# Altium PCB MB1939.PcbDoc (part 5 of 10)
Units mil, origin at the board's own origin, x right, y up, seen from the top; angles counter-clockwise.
Board outline 5910.64 x 4335.93 mil, 6 copper layers (Top Layer, l2_GND, L3_SIG, L4_VCC, L5_GND, Bottom Layer), stack 58.424 mil thick; 635 components, 489 nets, 2289 pads, 1388 vias.
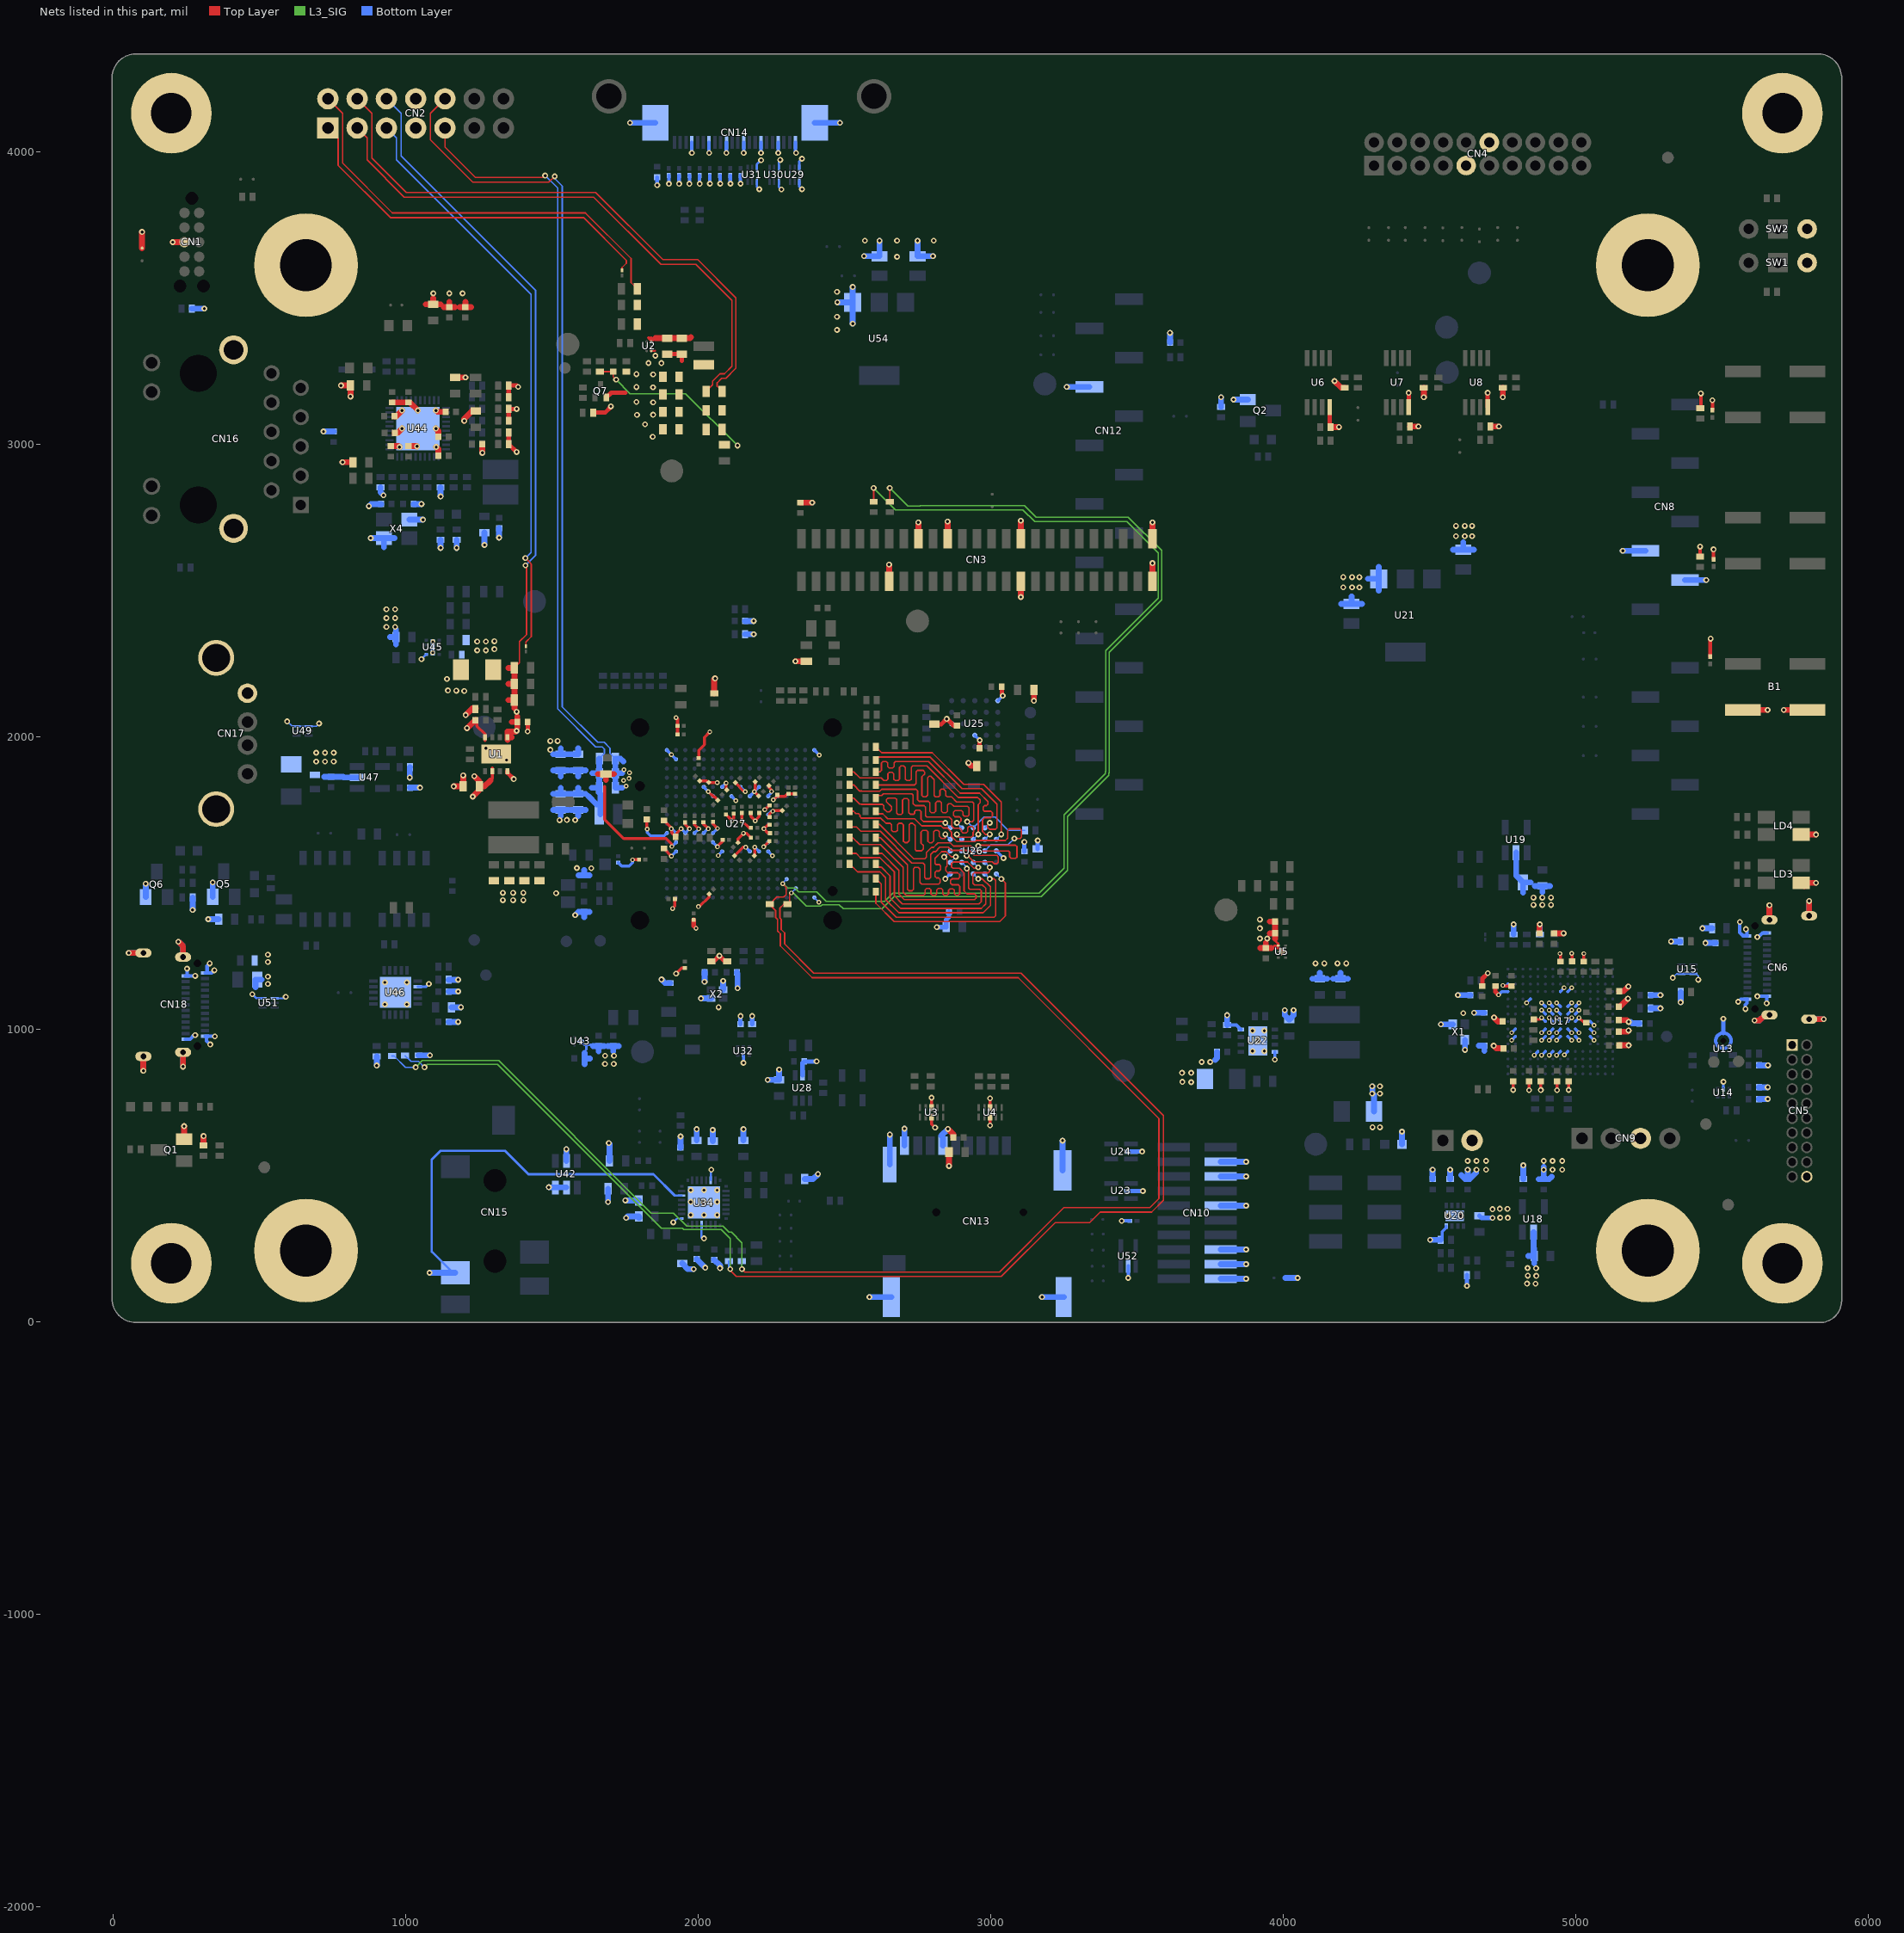
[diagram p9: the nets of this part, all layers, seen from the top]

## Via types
v1: diameter 20, hole 10, Top Layer to Bottom Layer, tented both sides, 1072 vias
v2: diameter 16, hole 8, Top Layer to Bottom Layer, tented both sides, 316 vias

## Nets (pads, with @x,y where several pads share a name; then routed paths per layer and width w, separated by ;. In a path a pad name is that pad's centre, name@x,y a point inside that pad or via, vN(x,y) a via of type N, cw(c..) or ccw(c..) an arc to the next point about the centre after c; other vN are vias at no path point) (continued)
GND: B1.3 B1.4 C1.1 C2.1 C3.1 C4.1 C5.1 C6.1 C7.1 C8.1 C9.1 C10.1 C11.1 C12.1 C13.1 C14.1 C15.1 C16.1 C17.1 C18.1 C19.2 C20.1 C21.1 C22.1 C24.1 C25.1 C26.1 C28.1 C29.1 C31.1 C32.1 C33.2 C34.1 C35.1 C36.1 C37.1 C38.1 C39.1 C40.1 C41.1 C42.1 C43.2 C44.1 C45.1 C46.1 C47.1 C48.1 C49.1 C50.1 C51.1 C52.1 C54.1 C55.1 C56.1 C57.1 C58.1 C59.1 C60.1 C61.1 C62.1 C63.1 C64.1 C65.1 C66.1 C67.1 C68.1 C69.1 C70.1 C71.1 C72.1 C73.1 C74.1 C75.1 C76.1 C77.1 C78.1 C79.1 C80.1 C81.2 C84.1 C85.2 C86.1 C87.1 C88.1 C89.1 C90.1 C91.1 C92.1 C94.1 C95.1 C96.2 C97.2 C98.2 C99.2 C100.2 C101.2 C102.2 C103.2 C104.2 C105.2 C106.2 C107.2 C108.2 C109.2 C110.2 C111.2 C112.2 C113.2 C114.2 C115.1 C116.1 C117.1 C118.1 C119.1 C120.2 C121.1 C122.1 C123.1 C124.1 C125.1 C126.1 C127.2 C128.1 C129.1 C130.1 C131.1 C132.1 C133.1 C134.1 C135.1 C136.1 C137.1 C138.1 C139.1 C140.2 C141.1 C142.1 C143.1 C144.1 C145.1 C146.1 C147.1 C148.1 C149.1 C150.1 C151.1 C152.1 C153.1 C155.1 C158.2 C159.1 C161.1 C162.1 C163.2 C167.2 C168.1 C169.1 C171.1 C172.1 C173.1 C174.1 C175.1 C176.1 C177.1 C178.1 C179.1 C180.1 C181.1 C183.1 C185.2 C186.1 C187.1 C188.1 C189.1 C190.1 C191.1 C193.1 C194.2 C195.1 C197.1 C198.1 C199.1 C200.1 C201.1 CN1.3 CN2.7 CN2.8 CN3.1 CN3.2 CN3.19 CN3.20 CN3.30 CN3.34 CN3.37 CN4.5 CN4.16 CN5.1 CN5.20 CN6.A1 CN6.A12 CN6.B1 CN6.B12 CN6.SH1 CN6.SH2 CN6.SH3 CN6.SH4 CN8.6 CN8.7 CN9.3 CN10.3 CN10.5 CN10.9 CN10.15 CN10.17 CN10.19 CN12.7 CN13.6 CN13.9 CN13.11 CN13.12 CN13.13 CN13.14 CN14.1 CN14.4 CN14.7 CN14.10 CN14.13 CN14.16 CN14.19 CN14.S1 CN14.S2 CN15.3 CN16.15 CN16.16 CN17.4 CN17.5 CN17.6 CN18.A1 CN18.A12 CN18.B1 CN18.B12 CN18.SH1 CN18.SH2 CN18.SH3 CN18.SH4 H1.1 H2.1 H3.1 H4.1 H5.1 H6.1 H7.1 H8.1 JP1.2 LD3.3 LD4.3 LD5.2 Q1.2 Q2.2 Q5.2 Q6.2 Q7.2 R3.1 R10.1 R13.1 R14.1 R15.1 R16.1 R17.1 R18.1 R29.1 R32.2 R33.2 R34.2 R41.1 R82.1 R83.1 R86.1 R87.1 R90.1 R91.1 R107.2 R108.2 R109.2 R115.2 R118.1 R119.2 R123.2 R125.1 R128.2 R133.1 R134.1 R150.1 R151.1 R164.1 R165.1 R189.1 R190.1 R192.2 R194.1 R195.1 R197.2 R201.1 R208.2 R210.1 R214.2 R215.1 R218.1 R223.1 R224.1 R225.1 SB1.1 SB54.1 SW1.3 SW2.3 U1.4 U1.8 U1.9 U2.C2 U3.3 U3.8 U4.3 U4.8 U5.2 U5.5 U6.4 U7.4 U8.4 U9.2 U10.2 U12.2 U13.3 U14.2 U15.3 U15.4 U16.2 U17.D5 U17.D6 U17.D7 U17.D8 U17.D9 U17.F2 U17.F6 U17.F7 U17.F8 U17.F9 U17.F10 U17.F12 U17.G2 U17.G6 U17.G7 U17.G8 U17.G9 U17.G10 U17.G12 U17.H6 U17.H7 U17.H8 U17.H9 U17.H10 U17.H12 U17.J6 U17.J7 U17.J8 U17.J9 U17.J10 U17.K6 U17.K7 U17.K8 U17.K9 U17.K10 U17.L4 U17.M1 U17.M8 U17.M9 U17.N1 U18.2 U19.2 U20.8 U20.9 U21.1 U22.4 U22.8 U22.9 U23.2 U24.2 U25.B3 U25.C1 U25.E5 U26.C1 U26.E5 U27.A17 U27.F2 U27.F7 U27.F10 U27.F11 U27.F12 U27.G6 U27.G12 U27.H1 U27.H2 U27.H3 U27.H4 U27.H5 U27.H6 U27.K12 U27.M6 U27.M8 U27.M10 U27.M12 U27.M13 U27.N5 U27.N7 U27.N9 U27.N11 U27.T2 U27.U1 U27.u17 U28.2 U29.3 U29.4 U30.3 U30.4 U31.3 U31.4 U32.2 U33.2 U34.5 U34.9 U34.14 U34.22 U34.33 U35.2 U36.2 U37.2 U38.2 U39.2 U40.2 U41.2 U42.2 U42.3 U42.5 U43.2 U43.5 U44.41 U45.5 U45.EP U46.12 U46.21 U47.2 U48.2 U49.3 U49.4 U50.2 U51.3 U51.4 U52.2 U53.2 U54.1 X1.2 X1.4 X2.2 X2.4 X4.2 X4.4 | length 19268.2
  Top Layer w8: U2.C2@1840,3318.5 1852.2,3318.5 ; 3970,1285 3970.28,1285.28 U5.2@3982.21,1285.27 3982.2,1292.8 3975,1300
  Top Layer w10: C20.1@1239.28,2056 C20.1@1239.56,2055.72 ; C20.1@1239.56,2057.28 C20.1@1239.56,2055.72 ; 1271.55,1987.24 1271.55,1998 U1.4@1271.62,1998.07 1271.62,2008.38 1244,2036 1244,2051.28 C20.1@1239.56,2055.72 ; v2(1776,1579) 1777,1580 C28.1@1798,1580 ; C29.1@1825,1717.28 1825,1685 v2(1826,1684) ; C34.1@1880,1617.72 C34.1@1883.2,1617.72 v2(1909.12,1591.8) ; C35.1@1884,1713.28 1908.59,1688.69 v2(1908.59,1685.01) 1909.74,1683.86 1909.74,1671.53 1923.28,1657.98 C37.1@1923.28,1657 1928,1661.72 1928,1671.14 v2(1941.88,1685.01) ; v2(1912.6,1412.6) 1920.83,1420.83 C36.1@1920.83,1445 ; v1(1925,1190) 1944.17,1209.17 C40.1@1955,1209.17 ; C41.1@1956,1707 1956,1699.88 v2(1970.87,1685.01) v2@1970.87,1688.3 ; C45.1@1988,1707.17 1988,1698.83 v2(2002,1684.83) ; v2(2001,1419) 2004,1419 2037.34,1452.34 C50.1@2037.34,1462.34 ; C46.1@2002.1,1926.23 2002.1,1953.1 2021.8,1972.8 2021.8,1997.8 v2(2040.1,2016.1) ; C44.1@2005.66,1849.24 2028.98,1849.24 2037.16,1841.06 2038.75,1842.65 v2(2065.4,1842.65) ; C48.1@2018,1707.17 2018,1701.83 v2(2034.82,1685.01) ; v2(2035.05,1812.23) 2053.39,1793.89 2056.43,1793.89 C51.1@2067.68,1782.64 ; C52.1@2051,1709.17 2051,1701.71 v2(2066.53,1686.18) ; v2(2066.4,1623.29) 2066.4,1624.6 2084.17,1642.37 C55.1@2084.18,1647 ; C57.1@2095,1734.17 2115,1714.17 v2(2115,1712.39) 2121.48,1718.87 C60.1@2121.48,1736.85 ; v2(2095.85,1841.49) 2095.85,1819.47 C54.1@2097.68,1817.64 ; C59.1@2125.14,1593.06 2153.81,1621.73 v2(2162.63,1621.73) ; C61.1@2127.35,1842.33 2157.41,1812.27 v2(2161,1812.27) ; C58.1@2135.86,1637.76 2135.86,1650.86 v2(2155,1670) 2165.69,1670 C66.1@2180.69,1655.01 ; C63.1@2150,1739.17 v2(2150,1712.39) 2174.38,1688.01 C67.1@2180.85,1688.01 ; C65.1@2180,1739.17 2180,1727.39 v2(2195,1712.39) 2209,1726.39 C70.1@2209,1739.17 ; C64.1@2192.68,1592.64 2194.1,1594.08 2194.1,1620.9 2193.93,1621.07 v2(2193.93,1621.93) ; C68.1@2194.87,1845.33 2194.86,1814.58 v2(2192.5,1812.22) C69.1@2207.35,1797.37 ; v2(2224.02,1623.3) C72.1@2243.69,1643.01 C72.1@2243.69,1643.01 ; v2(2228.15,1749.9) 2228.25,1750 2229.17,1750 C74.1@2244.18,1765 ; C71.1@2242.35,1832.33 2242.35,1826.66 2251,1818.01 2251,1812.92 v2(2251.24,1812.68) ; C73.1@2244.18,1725 2244.17,1735 2254.17,1745 v2(2255.05,1745.04) v2(2255.05,1745.04) v2(2255.05,1745.04) 2257.34,1747.33 C78.1@2287.35,1747.33 ; C75.1@2244.69,1699.01 2239.01,1699.01 v2(2225,1685) 2239.99,1670.01 C76.1@2245.69,1670.01 ; v2(2257.04,1783.74) 2271,1797.7 C77.1@2271,1801.17 2276.17,1796 2297.31,1796 2305.48,1804.17 C80.1@2331,1804.17 ; U3.3@2798,699.86 2798,676 v1(2810,664) ; U3.8@2798,732.14 v1(2798,766) ; v1(2998,671) U4.3@2998,699.86 ; U4.8@2998,730.14 U4.8@2998,732.14 v1(2998,764) ; 3959.05,1277.72 3982.28,1277.72 U5.5@3995.01,1264.99 ; v2(4750.07,1149.67) 4752.46,1147.28 C99.2@4780,1147.28 ; C100.2@4785,822.28 4785,792.82 v1(4785.25,792.57) ; v1(4839.6,791.89) 4840,792.29 C101.2@4840,822.28 ; C102.2@4856.69,1033.7 4877.2,1033.7 v2(4882.7,1039.2) ; v1@4879.6,791.85 v1(4880,792.25) C104.2@4880,822.28 ; C106.2@4935,822.28 4935,792.36 v1(4935.4,791.96) ; v2(4945.17,1258.46) 4945.17,1257.93 4946.69,1256.41 C107.2@4946.69,1231.42 ; C108.2@4975,822.28 v1(4975,792.4) v1@4975.4,792 ; v2(4985.12,1258.89) 4985.12,1258.01 4986.69,1256.44 C109.2@4986.69,1231.85 ; v2(5010.65,1039.2) 5027.57,1022.28 C111.2@5035,1022.28 ; C110.2@5026.69,1231.42 5026.69,1257.53 5027.01,1257.85 v2(5027.01,1258.46)
  Top Layer w12: v2(1924.81,2064.75) v2(1924.81,2064.75) 1929.68,2059.82 C38.1@1929.69,2007.01 ; R225.1@5424.29,2615.43 v1(5424.29,2649.41) ; R224.1@5425,3122.72 5426.8,3124.52 v1(5426.8,3172.7) ; U9.2@5458.74,2273.35 5458.74,2333.74 v1(5460,2335) ; U12.2@5466.26,3115.87 v1(5466.26,3149.84) ; U10.2@5470,2606.03 v1(5470,2640)
  Top Layer w15: U1.8@1348.39,1881.93 1348.39,1876.61 v1(1370,1855) ; R14.1@1352.72,3040 R13.1@1352.72,3000 v1(1380,2972.72) ; R15.1@1352.72,3080 R16.1@1352.72,3120 v1(1380,3120) ; R17.1@1352.72,3160 R18.1@1352.72,3200 1380,3200 v1(1385,3195) ; v1(1417.72,2017.72) C24.1@1417.72,2050 ; R223.1@1641.32,3107.4 1682.4,3107.4 1701.9,3126.9 v1(1701.9,3128.7) ; Q7.2@1686.59,3158.99 1703.29,3175.7 1752.4,3175.7 ; C31.1@1895,3307.44 1945,3307.44 C32.1@1945,3306.69 1945,3285 ; C43.2@1985,1374.17 1985,1353 v2(1993,1345) ; R32.2@2045,1232.28 2053.86,1232.28 v1(2072.72,1251.14) 2091.58,1232.28 R34.2@2100,1232.28 ; C84.1@2808,2042.44 2831.44,2042.44 v1(2849.89,2060.89) 2873.5,2037.28 C87.1@2885,2037.28 ; C89.1@2962.29,1960 2962.39,1960.11 v1(2962.39,1987.76) ; C90.1@3037.72,2170 3037.72,2143.04 v1(3041.13,2139.63) ; U6.4@4158.39,3126.34 4158.39,3060.85 R82.1@4161.23,3058.01 ; U7.4@4428.39,3126.34 v1(4428.39,3175) ; C33.2@4680,1147.72 4680,1172.95 v1(4698.52,1191.48) ; U8.4@4698.39,3126.34 v1(4698.39,3175) ; C96.2@4725,1147.28 4725,1127.46 v2(4735.07,1117.39)
  Top Layer w20: v1(54.3,1260.71) CN18.SH4@104.38,1260.71 ; SB1.1@100,3669.68 v1(100,3725) ; v1(104.38,857.62) CN18.SH3@104.38,907.16 ; v1(205,3690) CN1.3@245.02,3690 ; v1(224,1299) 240.2,1282.8 CN18.SH2@240.2,1246.53 ; v1(240.2,872) CN18.SH1@240.2,921.34 ; Q1.2@243.82,624.41 v1(243.82,668.82) ; R3.1@310,602.72 v1(310,635) ; v1(780,3200) C1.1@812.45,3200 v1(812.44,3162.56) ; v1(785,2937.83) C2.1@820.08,2937.83 ; C5.1@950,2992.72 977.28,2992.72 v1(980,2990) ; C6.1@955,3142.28 1015.18,3142.28 v1(1042.63,3114.83) ; C3.1@962.72,3095 968.36,3095 v1(988.36,3115) ; C4.1@963.89,3037.87 973.23,3037.87 v1(988.36,3053) ; C7.1@1010,2992.72 1038.74,2992.72 v1(1039.63,2991.83) ; 1069.46,3477.56 C9.1@1095,3477.56 ; 1095,3498.18 C9.1@1095,3477.56 ; v1(1104,3053) 1112.28,3044.72 C11.1@1112.29,3025 ; v1(1104,3115) 1109,3110 C12.1@1137.29,3110 ; v1(1105,2990) 1112.28,2982.72 C10.1@1112.29,2960 ; 1120.54,3477.56 C9.1@1095,3477.56 ; 1130.95,3467.72 C13.1@1150,3467.72 ; 1150,3485.78 C13.1@1150,3467.72 ; v1(1165,1830) C16.1@1197.45,1830 v1(1197.44,1867.44) ; 1169.05,3467.72 C13.1@1150,3467.72 ; C14.1@1170,3227.56 v1(1205,3227.56) ; 1185.95,3467.72 C17.1@1205,3467.72 ; v1(1201.1,3078.9) 1201.1,3086.1 1227.56,3112.56 C19.2@1240,3112.56 ; 1205,3485.78 C17.1@1205,3467.72 ; v1(1206,2074) 1228,2096 R10.1@1240.28,2096 ; v1(1210,2029) 1211.28,2029 C20.1@1239.56,2057.28 ; 1224.05,3467.72 C17.1@1205,3467.72 ; v1(1262.72,2970) C18.1@1262.72,3000 ; R33.2@2055,2147.72 2055,2196 v1(2058,2199) ; v1(2332.56,2257.44) R41.1@2370,2257.44 ; C81.2@2350,2800 v1(2390,2800) ; CN3.37@2652.87,2531.12 v1(2652.87,2587.87) ; CN3.34@2752.87,2676.22 v1(2752.87,2732.13) ; CN3.30@2852.87,2676.22 v1(2852.87,2735) ; v1(2854,659) 2872.28,640.72 C86.1@2872.29,630 ; v1(2857.44,532.56) C85.2@2857.45,580 ; v1(2924,1910) 2934,1900 C88.1@2952.45,1900 ; v1(3102.87,2477.13) CN3.19@3102.87,2531.12 ; CN3.20@3102.87,2676.22 v1(3102.87,2737.87) ; v1(3147.56,2122.44) C91.1@3147.56,2160 ; CN3.1@3552.87,2531.12 v1(3552.87,2592.87) ; CN3.2@3552.87,2676.22 v1(3552.87,2732.13) ; 3920.95,1277.72 C92.1@3940,1277.72 ; 3940,1295.78 C92.1@3940,1277.72 ; 3953.71,1327.99 C94.1@3971.78,1327.99 ; 3953.71,1367.99 C95.1@3971.78,1367.99 3971.77,1348.94 ; 3959.05,1277.72 C92.1@3940,1277.72 ; 3971.77,1308.94 C94.1@3971.78,1327.99 ; 3971.77,1347.04 C94.1@3971.78,1327.99 ; R82.1@4161.23,3058.01 v1(4190,3058.01) ; v1(4175,3215) 4197.72,3192.28 R83.1@4210,3192.28 ; R86.1@4432.72,3060 v1(4461.49,3060) ; v1(4480,3160) R87.1@4480,3192.28 ; R90.1@4707.72,3060 v1(4736.49,3060) ; v1(4718.7,943.7) 4727.4,935 C98.2@4752.29,935 ; v1(4720,1040) 4733.58,1026.42 C97.2@4748.98,1026.42 ; v1(4750,3160) R91.1@4750,3192.28 ; C103.2@4875,1327.72 4875,1356.62 v1(4876.69,1358.31) ; C105.2@4925,1327.72 v1(4957.72,1327.72) ; C112.2@5146.7,991.42 5175.52,991.42 v1(5179.72,995.62) ; C113.2@5146.7,1031.42 5173.58,1031.42 v1(5180,1025) ; C114.2@5146.7,1076.42 5149.47,1076.42 v1(5177.55,1104.5) ; C115.1@5147.72,945 v1(5180,945) ; C116.1@5147.72,1130 5163.22,1130 v1(5179.11,1145.89) ; B1.3@5523.5,2081.42 5533.34,2091.26 B1.3@5569.77,2091.26 v1(5655,2091.26) ; v1(5610,1030) 5627.65,1030 5646.22,1048.58 CN6.SH2@5661.15,1048.58 ; CN6.SH1@5661.15,1373.77 v1(5661.15,1423.85) ; v1(5710,2091.26) B1.4@5790.24,2091.26 5826.66,2091.26 B1.4@5836.5,2081.42 ; LD4.3@5769.06,1665.47 v1(5820.47,1665.47) ; LD3.3@5780.47,1489.06 LD3.3@5769.06,1500.47 v1(5820.47,1500.47) ; CN6.SH4@5796.97,1034.4 v1(5847.05,1034.4) ; CN6.SH3@5796.97,1387.95 v1(5796.97,1438.03)
  Bottom Layer w5: v1(596,2052) 612.9,2035.1 U49.3@627.98,2035.1 ; U49.3@629.33,2035.75 695.75,2035.75 v1(705,2045) ; 1636.54,946.69 1640.95,942.28 ; U27.A17@2397.32,1450.04 U27.A17@2401.16,1446.19 ; U27.A17@2401.16,1446.16 v2(2413.01,1434.31) ; v1(5331,1176) 5344.25,1189.25 U15.4@5360.33,1189.25 U15.3@5401.67,1189.25 5411.75,1189.25 5418,1183 v1(5418,1169)
  Bottom Layer w7: U51.4@553.67,1105.75 585.75,1105.75 v1(591,1111) ; v1(1055,2265) U45.5@1071.57,2281.57 ; v1(1915,340) 1927.85,352.85 U34.9@1943.86,352.85 ; U34.5@2011.77,332.18 2011.77,286.77 2013.54,285 v1(2020,285) ; U34.22@2043.27,483.76 v1@2043.27,518.27
  Bottom Layer w8: v1(476.5,1119.8) 490.35,1105.95 U51.3@512.33,1105.95 ; CN15.3@1170.01,167.8 1162.2,167.8 1090,240 1090,555 1119.5,584.5 1340.5,584.5 1420.5,504.5 1847.42,504.5 1920.33,431.59 U34.14@1943.86,431.59 ; U43.5@1598,959.49 1610.79,946.69 U43.2@1618.27,946.69 ; 1618.27,931.53 U43.2@1618.27,946.69 ; 1636.54,946.69 U43.2@1618.27,946.69 ; v1(1694.88,610.63) v1@1697.44,608.07 ; U31.4@2200.75,3899.33 2200.75,3879.18 v1(2209.26,3870.67) ; U31.3@2200.75,3940.67 2200.75,3955.75 2215,3970 v1(2215.35,3970) ; U30.4@2275.75,3899.33 2275.75,3879.25 v1(2285,3870) ; U30.3@2275.75,3940.67 2275.75,3965.75 v1(2281.02,3971.02) ; U29.4@2345.75,3899.33 2345.75,3879.92 v1(2355,3870.67) ; U29.3@2345.75,3940.67 2345.75,3965.75 v1(2355,3975) ; U14.2@5503.84,794.97 v1(5503.84,820.31)
  Bottom Layer w9: v1@2043.27,518.27 v1(2045,520)
  Bottom Layer w10: U46.12@1041.8,1145.39 1070.38,1145.38 v1(1080,1155) ; U45.5@1071.57,2281.57 U45.5@1071.89,2281.57 ; C169.1@1727,1569.76 1738.76,1558 1765,1558 1776,1569 v2(1776,1579) ; v2(1826,1684) 1826,1672 1838,1660 1882.87,1660 U27.H1@1893.38,1670.51 ; U27.U1@1893.38,1953.98 1893.38,1953.84 v2(1909.03,1938.19) 1921.92,1925.3 1922.05,1925.3 U27.T2@1924.88,1922.48 ; v2(1908.59,1685.01) 1910.37,1685.01 U27.H2@1924.88,1670.51 ; v2(1909.12,1591.8) U27.F2@1924.84,1607.52 ; v2(1941.88,1685.01) U27.H3@1956.37,1670.51 v2(1970.87,1685.01) ; U27.H4@1987.87,1670.51 2002,1684.65 v2(2002,1684.83) ; U27.H5@2019.36,1670.51 2033.86,1685.01 v2(2034.82,1685.01) ; U27.N5@2019.36,1827.99 2034.74,1812.61 2034.74,1812.54 v2(2035.05,1812.23) 2036.94,1810.34 2037.02,1810.34 U27.M6@2050.86,1796.5 ; U27.G6@2050.86,1639.02 2066.4,1623.48 v2(2066.4,1623.29) ; U27.H6@2050.86,1670.51 v2(2066.53,1686.18) ; v2(2068.42,1593.59) U27.F7@2082.35,1607.52 ; U27.N7@2082.35,1827.99 v2(2095.85,1841.49) ; U27.M8@2113.85,1796.5 v2(2129.33,1781.02) ; U27.N9@2145.35,1827.99 2145.34,1827.93 v2(2161,1812.27) ; v1(2155,885) U32.2@2154.99,913.19 ; v2(2162.63,1621.73) U27.F10@2176.84,1607.52 ; U27.M10@2176.84,1796.5 2176.84,1796.56 v2(2192.5,1812.22) U27.N11@2208.34,1827.99 U27.N11@2208.34,1827.99 ; v2(2193.93,1621.93) U27.F11@2208.34,1607.52 ; v2(2224.02,1623.3) 2239.74,1639.02 U27.G12@2239.84,1639.02 ; U27.F12@2239.84,1607.52 v2(2254.37,1592.98) ; U27.M12@2239.84,1796.5 2239.83,1798.5 2251,1809.67 2251,1812.44 v2(2251.24,1812.68) ; U27.K12@2239.84,1733.51 2251.33,1745 v2(2255.05,1745.04) v2(2255.05,1745.04) v2(2255.05,1745.04) ; v2(2257.04,1783.74) 2269.8,1796.5 U27.M13@2271.33,1796.5 ; U27.u17@2397.32,1953.98 v2(2414.32,1936.97) ; v1(2844.89,1514.02) U26.E5@2861.77,1530.9 ; v1(2849.89,2060.89) U25.C1@2866.77,2044.01 ; U25.B3@2945.51,2004.64 v1(2962.39,1987.76) ; U26.C1@3019.25,1609.64 v1(3043.95,1584.94) ; U25.E5@3024.25,2122.75 v1(3041.13,2139.63) ; v1(3971.06,896.06) U22.8@3971.07,922.12 ; R128.2@4537.29,280 4542.28,285 4542.28,307.58 4556.45,321.75 U20.8@4556.45,327.01 ; v2(4735.07,1117.39) 4746.46,1128.78 U17.M1@4767.56,1128.78 ; v2(4750.07,1149.67) 4762.85,1149.67 U17.N1@4767.55,1154.37 ; v2(4780.34,962.43) U17.F2@4793.15,975.24 ; v2(4780.34,988.02) U17.G2@4793.15,1000.83 ; v2(4831.53,1090.37) U17.L4@4844.33,1103.19 ; v2(4857.11,911.25) U17.D5@4869.92,924.06 ; v2(4882.7,911.25) U17.D6@4895.51,924.06 ; v2(4882.7,962.43) U17.F6@4895.51,975.24 ; v2(4882.7,988.02) U17.G6@4895.51,1000.83 ; v2(4882.7,1039.2) U17.H6@4895.51,1026.42 ; v2(4882.7,1064.79) U17.J6@4895.51,1052.01 ; v2(4882.7,1090.39) U17.K6@4895.51,1077.6 ; v2(4908.29,911.25) U17.D7@4921.1,924.06 ; v2(4908.29,962.43) U17.F7@4921.1,975.24 ; v2(4908.29,988.02) U17.G7@4921.1,1000.83 ; v2(4908.29,1039.2) U17.H7@4921.1,1026.42 ; v2(4908.29,1064.79) U17.J7@4921.1,1052.01 ; v2(4908.29,1090.39) U17.K7@4921.1,1077.6 ; v2(4933.88,911.25) U17.D8@4946.7,924.06 ; v2(4933.88,962.43) U17.F8@4946.7,975.24 ; v2(4933.88,988.02) U17.G8@4946.7,1000.83 ; v2(4933.88,1039.2) U17.H8@4946.7,1026.42 ; v2(4933.88,1064.79) U17.J8@4946.7,1052.01 ; v2(4933.88,1090.39) U17.K8@4946.7,1077.6 ; U17.M8@4946.7,1128.78 v2(4959.48,1141.57) ; v2(4960.31,912.09) U17.D9@4972.29,924.06 ; U17.F9@4972.29,975.24 v2(4985.06,962.43) ; U17.G9@4972.29,1000.83 v2(4985.06,988.02) ; U17.H9@4972.29,1026.42 v2(4985.06,1039.2) ; U17.J9@4972.29,1052.01 v2(4985.06,1064.79) ; U17.K9@4972.29,1077.6 v2(4985.06,1090.39) ; U17.M9@4972.29,1128.78 v2(4985.07,1141.57) ; U17.F10@4997.88,975.24 v2(5010.65,962.43) ; U17.G10@4997.88,1000.83 v2(5010.65,988.02) ; U17.H10@4997.88,1026.42 v2(5010.65,1039.2) ; U17.J10@4997.88,1052.01 v2(5010.65,1064.79) ; U17.K10@4997.88,1077.6 v2(5010.65,1090.39) ; U17.F12@5049.05,975.24 v2(5061.83,962.43) ; U17.G12@5049.05,1000.82 v2(5061.83,988.02) ; U17.H12@5049.04,1026.41 v2(5061.83,1013.61)
  Bottom Layer w12: CN18.B12@248.47,965.82 264.03,965.82 278.2,980 v1(281.6,980) ; CN18.B1@248.47,1182.36 CN18.B1@253.64,1182.36 ; v1(253.74,1207) 253.74,1182.45 CN18.B1@253.64,1182.36 ; v1(281.74,1182.36) CN18.B1@253.64,1182.36 ; CN18.A1@315.4,975.67 CN18.A1@320.57,975.67 ; CN18.A12@315.4,1192.2 CN18.A12@322.2,1192.2 ; v1(331,1225) 322.3,1216.3 322.3,1192.3 CN18.A12@322.2,1192.2 ; v1(333,948) 320.67,960.33 320.67,975.57 CN18.A1@320.57,975.67 ; v1(347,1201.41) 337.8,1192.2 CN18.A12@322.2,1192.2 ; v1(348.67,975.67) CN18.A1@320.57,975.67 ; C161.1@1860,3912.28 1860,3885.13 v1(1860.52,3884.61) ; U41.2@1900,3917.7 1900.52,3917.18 v1(1900.52,3889.61) ; U40.2@1935,3917.7 1935,3890.13 v1(1935.52,3889.61) ; U39.2@1970,3917.7 1970.43,3917.27 1970.43,3889.7 v1(1970.52,3889.61) ; v1(1978.67,3995) CN14.19@1978.67,4030.71 ; U38.2@2005,3917.7 2005,3890.13 v1(2005.52,3889.61) ; v1(2037.73,3995) CN14.16@2037.72,4030.71 ; U37.2@2040,3917.7 2040,3890.52 v1(2040.52,3890) ; U36.2@2075,3917.7 2075,3890.52 v1(2075.52,3890) ; v1(2096.78,3995) CN14.13@2096.78,4030.71 ; U35.2@2110,3917.7 2110,3890.52 v1(2110.52,3890) ; v1(2145,3890) U33.2@2145,3917.7 ; v1(2155.83,3995) CN14.10@2155.83,4030.71 ; v1(2214.89,3995) CN14.7@2214.89,4030.71 ; v1(2273.94,3995) CN14.4@2273.94,4030.71 ; CN14.1@2333,4030.71 2332.99,3997.01 v1(2335,3995) ; v1(3447.7,345) U53.2@3475.39,345 ; v1(3470,150) U52.2@3470,191.54 ; R133.1@3807.95,1014.85 3838.97,1014.85 U22.4@3854.92,998.89 ; v1(5554.35,1093.7) 5563.55,1102.91 CN6.A12@5585.09,1102.91 ; v1(5560,1366.31) 5560,1330 5570.56,1319.44 CN6.A1@5585.09,1319.44 ; v1(5579,1069) 5579,1083 5585,1089 5585,1102.81 CN6.A12@5585.09,1102.91 ; v1(5581,1342) 5585,1338 5585,1319.54 CN6.A1@5585.09,1319.44 ; CN6.A12@5585.95,1102.91 CN6.A12@5585.09,1102.91 ; CN6.A1@5585.95,1319.44 CN6.A1@5585.09,1319.44 ; v1(5619.61,1112.75) CN6.B1@5651.75,1112.75 ; v1(5619.75,1315.11) 5623.15,1315.11 5637.32,1329.29 CN6.B12@5652.88,1329.29 ; v1(5651.66,1088.66) 5651.66,1112.66 CN6.B1@5651.75,1112.75 ; CN6.B1@5652.88,1112.75 CN6.B1@5651.75,1112.75
  Bottom Layer w15: C152.1@2145,1017.72 v1(2145,1045) ; R150.1@2185,1017.72 v1(2185,1045) ; U28.2@2357.02,842.8 2357.01,884.29 C145.1@2362.72,890 v1(2405,890) ; v1(2815.99,1349.01) 2847.95,1349.01 2847.95,1373.95 2857.79,1383.79 C144.1@2857.8,1402.01 ; C142.1@3115,1607.72 v1(3115,1640) ; C141.1@3160.51,1616.57 v1(3160.51,1645) ; U23.2@3478.98,447.01 v1(3520,447.01) ; U24.2@3478.98,582.01 v1(3517.59,582.01) ; v1(4627.28,122.72) R123.2@4627.28,160 ; C129.1@4670,362.56 4677.56,355 v1(4715,355) ; U13.3@5503.69,987.06 v1(5503.68,1035.52)
  Bottom Layer w20: v1(54.3,1260.71) CN18.SH4@104.38,1260.71 ; v1(104.38,857.62) CN18.SH3@104.38,907.16 ; Q6.2@112.6,1451.69 v1(112.6,1497.6) ; v1(224,1299) 240.2,1282.8 CN18.SH2@240.2,1246.53 ; v1(240.2,872) CN18.SH1@240.2,921.34 ; R218.1@270.35,3462.83 v1(312.83,3462.83) ; v1(272.72,1407.72) R215.1@272.72,1450 ; v1(325.94,1375.94) R214.2@361.45,1375.94 ; Q5.2@341.6,1452.63 v1(341.6,1501.6) ; C197.1@487.74,1143.71 487.74,1169.25 C197.1@493.65,1169.25 C197.1@508.36,1169.25 ; v1(720,3042.72) C193.1@755,3042.72 ; 722.28,1862.72 C194.2@745,1862.72 787.28,1862.72 789.49,1860.51 U47.2@834.69,1860.51 ; v1(875,2787.5) 882.5,2795 C191.1@917.29,2795 ; v1(881.5,2678.5) X4.2@926.7,2678.5 ; v1(902.01,875.99) R210.1@902.01,906.77 ; R208.2@915,2852.28 915,2835 v1(925,2825) ; 926.69,2646.86 X4.2@926.7,2678.5 ; 946.82,2340 C189.1@967.45,2340 ; 962.27,2678.5 X4.2@926.7,2678.5 ; 967.44,2314.46 C189.1@967.45,2340 ; v1@967.44,2365.54 C189.1@967.45,2340 ; X4.4@1013.31,2741.5 v1(1060,2741.5) ; v1(1015,1860) 1015,1894.8 R201.1@1015.71,1895.51 ; C190.1@1015.71,1825.51 v1(1049.49,1825.51) ; C188.1@1027.72,2795 v1(1055,2795) ; R197.2@1045.01,910.77 v1(1083.57,910.77) ; v1(1082.2,167.8) 1162.2,167.8 CN15.3@1170.01,167.8 ; v1(1120,2645) R194.1@1120,2672.28 ; v1(1120,2820.82) R195.1@1120,2852.28 ; C186.1@1147.72,1025 v1(1180,1025) ; C187.1@1147.72,1129 v1(1180,1129) ; R192.2@1147.72,1169 v1(1180,1169) ; C185.2@1157.56,1075 v1(1189.84,1075) ; v1(1175,2645) R190.1@1175,2672.28 ; v1(1270,2655) C181.1@1270,2697.44 ; v1(1320,2680) C180.1@1320,2712.28 ; v1(1490,460) 1490.78,459.22 U42.3@1512.6,459.22 U42.2@1550,459.22 ; 1504.97,1749.45 C178.1@1530.51,1749.45 ; 1504.97,1939.57 C179.1@1530.51,1939.57 ; 1530.51,1728.83 C178.1@1530.51,1749.45 ; 1530.51,1960.19 C179.1@1530.51,1939.57 ; U42.5@1550,549.78 v1(1550,590) ; 1556.05,1749.45 C178.1@1530.51,1749.45 ; 1556.05,1939.57 C179.1@1530.51,1939.57 ; 1564.97,1749.45 C176.1@1590.51,1749.45 ; 1564.97,1939.57 C177.1@1590.51,1939.57 1590.51,1960.19 ; v1(1580,1390) 1590.97,1400.97 C174.1@1610.39,1400.97 ; 1590.51,1728.83 C176.1@1590.51,1749.45 ; 1591.34,1526.41 C175.1@1610.39,1526.41 ; 1610.39,1382.91 C174.1@1610.39,1400.97 ; 1610.39,1544.47 C175.1@1610.39,1526.41 ; 1612.72,880.95 C173.1@1612.72,900 ; 1612.72,919.05 C173.1@1612.72,900 ; 1616.05,1749.45 C176.1@1590.51,1749.45 ; 1629.44,1400.97 C174.1@1610.39,1400.97 ; 1629.44,1526.41 C175.1@1610.39,1526.41 ; 1630.78,900 C173.1@1612.72,900 ; 1640.95,942.28 C172.1@1660,942.28 ; 1660,924.22 C172.1@1660,942.28 ; 1679.05,942.28 C172.1@1660,942.28 ; 1690.95,942.28 C171.1@1710,942.28 ; v1(1692.44,409.37) R165.1@1692.44,455 ; R164.1@1697.44,550 v1@1697.44,608.07 ; 1710,924.22 C171.1@1710,942.28 ; 1729.05,942.28 C171.1@1710,942.28 ; v1(1751.81,415) C167.2@1797.44,415 ; v1(1754.25,355) 1759.25,360 C163.2@1797.44,360 ; v1(1767.64,4097.64) CN14.S2@1853.86,4097.64 ; C163.2@1797.44,355 C163.2@1799.88,355 ; v1(1875,1170) 1887.28,1157.72 C198.1@1905,1157.72 ; C162.1@1940,595.43 v1(1940,633.7) ; C148.1@1945.65,199.7 1965.35,180 v1(1985,180) ; C149.1@1995,214.57 v1(2024.57,185) ; C158.2@1995,620.12 v1(1995,658.39) ; v1(2010,1105.24) X2.4@2044.34,1105.24 ; v1(2022.28,1162.28) C155.1@2022.29,1195 ; C168.1@2050,617.56 v1(2050,655.83) ; C159.1@2055,212.28 2075,192.28 v1(2075,183.48) ; X2.2@2085.67,1134.76 v1(2085.67,1165) ; C153.1@2132.72,1195 2132.72,1191.38 2135,1189.1 v1(2135,1140) ; C147.1@2155,620.12 v1(2155,658.39) ; C151.1@2160.42,2395 v1(2190,2395) ; R151.1@2160.44,2350 v1(2190,2350) ; v1(2237.95,827.05) C146.1@2277.01,827.05 v1(2277.01,862.01) ; C150.1@2364.17,487.97 2392.98,487.97 v1(2410,505) ; CN14.S1@2398.74,4097.64 v1(2484.97,4097.64) ; v1(2475.7,3484.3) U54.1@2528.35,3484.3 ; v1(2528.35,3411.65) U54.1@2528.35,3484.3 ; v1(2528.35,3536.65) U54.1@2528.35,3484.3 ; v1(2567.35,3641.93) C200.1@2620,3641.93 v1(2620,3694.58) ; v1(2585.36,84.64) CN13.11@2660.99,84.64 ; CN13.14@2655.09,537.39 2655.08,569.99 v1(2655.07,639.93) ; CN13.9@2705.27,602.35 2705.27,619.99 v1(2705.26,660.26) ; v1(2750,3694.58) C199.1@2750,3641.93 v1(2802.65,3641.93) ; CN13.6@2837.16,602.35 2837.16,629.99 2831.08,636.07 v1(2854,659) ; v1(3175.36,84.64) CN13.12@3249.57,84.64 ; CN13.13@3245.64,517.71 3245.63,599.99 v1(3245.62,619.38) ; v1(3260,3195) CN12.7@3337.52,3195 ; C140.2@3612.8,3347.01 v1(3612.79,3380) ; 3767,895 3772.96,900.96 C139.1@3772.96,922.13 ; CN10.19@3785.76,147.01 v1(3872.99,147.01) ; CN10.17@3785.76,197.01 v1(3872.99,197.01) ; CN10.15@3785.76,247.01 v1(3872.99,247.01) ; CN10.9@3785.76,397.01 v1(3872.99,397.01) ; CN10.5@3785.76,497.01 v1(3872.99,497.01) ; CN10.3@3785.76,547.01 v1(3872.99,547.01) ; R134.1@3787.01,3127.21 v1(3787.01,3160) ; R133.1@3807.95,1014.85 v1(3807.95,1047.95) ; v1(3830,3151.89) Q2.2@3878.71,3151.89 ; v1(4005,1065) 4005,1047.56 C137.1@4020,1032.56 4035,1047.56 v1(4035,1065) ; SB54.1@4006.72,150 v1(4049,150) ; 4099.46,1172.56 C136.1@4125,1172.56 ; 4125,1193.18 C136.1@4125,1172.56 ; 4150.54,1172.56 C136.1@4125,1172.56 ; 4169.46,1172.56 C135.1@4195,1172.56 ; 4195,1193.18 C135.1@4195,1172.56 ; 4197.45,2453.62 C134.1@4233.03,2453.62 ; 4220.54,1172.56 C135.1@4195,1172.56 ; 4233.03,2479.36 C134.1@4233.03,2453.62 ; 4268.61,2453.62 C134.1@4233.03,2453.62 ; 4288.91,2539.49 U21.1@4326.46,2539.49 ; v1@4305,805 4305,780 4310,775 C201.1@4310,719 ; 4326.46,2498.99 U21.1@4326.46,2539.49 ; 4326.46,2579.99 U21.1@4326.46,2539.49 ; LD5.2@4405.54,606.38 v1(4405.54,650) ; v1(4501.6,280) R128.2@4537.29,280 ; C133.1@4510,487.72 v1(4510,520) ; v1(4538.43,1016.57) X1.2@4579.34,1016.57 ; R125.1@4570,487.72 v1(4570,520) ; 4579.42,2638.46 C131.1@4615,2638.46 ; v1(4596.42,1116.42) C130.1@4638.98,1116.42 ; 4608,501 4621.28,487.72 C132.1@4630,487.72 ; 4615,2664.2 C131.1@4615,2638.46 ; v1(4620.67,929.33) X1.4@4620.67,963.42 ; v1(4630,520) C132.1@4630,487.72 ; 4650.58,2638.46 C131.1@4615,2638.46 ; v1(4651.42,1056.42) C128.1@4686.69,1056.42 ; 4659,510 4636.72,487.72 C132.1@4630,487.72 ; 4667.64,943.7 C127.2@4686.69,943.7 4686.69,925.64 ; R119.2@4786.69,1324.14 v1(4786.69,1358.31) ; U19.2@4795.52,1603.7 4795.51,1525.47 C126.1@4818.98,1502.01 ; 4818.97,1466.43 C126.1@4818.98,1502.01 ; R118.1@4820,487.72 v1(4820,535) ; 4836.82,225 C123.1@4857.45,225 ; 4844.71,1502.01 C126.1@4818.98,1502.01 ; U18.2@4855.01,306.69 4855,227.44 C123.1@4857.45,225 ; 4857.44,199.46 C123.1@4857.45,225 ; 4857.44,250.54 C123.1@4857.45,225 ; 4859.97,1489.45 C124.1@4885.51,1489.45 ; 4873.28,487.72 C125.1@4890,487.72 ; R115.2@4876.69,1324.14 v1(4876.69,1358.31) ; 4885.51,1468.83 C124.1@4885.51,1489.45 ; 4890,530 v1(4890,520) C125.1@4890,487.72 ; 4911.05,1489.45 C124.1@4885.51,1489.45 ; 4917,496 4908.72,487.72 C125.1@4890,487.72 ; v1(5160,2635) CN8.6@5237.5,2635 ; v1(5180,1025) 5186.92,1025 5191.92,1020 C122.1@5217.29,1020 ; R109.2@5254.41,1071.42 v1(5288.58,1071.42) ; C121.1@5254.41,1116.42 v1(5288.58,1116.42) ; v1(5325,1300) R108.2@5357.29,1300 ; v1(5357.79,1092.21) R107.2@5357.8,1127.01 ; CN8.7@5372.48,2535 v1(5445,2535) ; v1(5432.48,1345) U16.2@5465.39,1345 ; v1(5442.48,1295) C120.2@5477.28,1295 ; v1(5610,1030) 5627.65,1030 5646.22,1048.58 CN6.SH2@5661.15,1048.58 ; C117.1@5625.1,761.51 v1(5655.19,761.51) ; C118.1@5625.1,801.51 v1(5655.19,801.51) ; C119.1@5625.1,876.51 v1(5656.18,876.51) ; CN6.SH1@5661.15,1373.77 v1(5661.15,1423.85) ; CN6.SH4@5796.97,1034.4 v1(5847.05,1034.4) ; CN6.SH3@5796.97,1387.95 v1(5796.97,1438.03)
  other v1: 4862,130 4833,130.7 4864.5,157.1 4835.5,157.8 4834.8,184 4863.8,183.3 4741,356 4767,355.69 4564.8,362.6 4606.8,362.3 1975,365 2020,365 2065,365 4715,385 4766,386 4740,386.31 2019.65,407.97 1975,410 2065,410 1975,450 2020,450 2065,450 4660,520 4693,520 4920,520 4953,520 4630,550 4660,550 4693,550 4890,550 4920,550 4953,550 4305,665 4330,665 4303.76,780 4330,780 4303.76,805 4330,805 3685,819 3655,820 3654,851 3685,851 1681.6,881.2 1712,881.2 3721,888 3750,888 1682.3,909.6 1712.7,909.6 3895,925 3935,925 3913,960.5 3895,995 3935,995 4615,1055 2070,1075 930,1085 1005,1085 966.01,1125.7 530,1155 930,1160 1005,1160 530,1180 4110,1225 4140,1225 4185,1225 4215,1225 530,1230 530,1255 3920,1310 3945,1310 3920,1345 3920,1375 4855,1425 4885,1425 4915,1425 1333,1441 1368,1441 1403,1441 4855,1450 4885,1450 4915,1450 1515,1465 1333,1466 1368,1466 1403,1466 1635,1550 1585.9,1550.9 1526.71,1714.36 1580.1,1715 1551.7,1715.3 695,1915 725,1915 755,1915 1345,1920 695,1945 725,1945 755,1945 1495,1955 1275,1960 1495,1985 1520,1985 1201,2156 1174,2157 1145,2158 1142,2197 1245,2295 1275,2295 1304,2299 1245,2325 1275,2325 1304,2326 935,2375 965,2375 935,2405 965,2405 935,2435 965,2435 4205,2510 4235,2510 4260,2510 4205,2545 4235,2545 4260,2545 4590,2685 4620,2685 4645,2685 4590,2720 4620,2720 4645,2720 1845,3025 1042.63,3052.83 1818.6,3067.4 1791.4,3099.9 1846.4,3100.2 1846.4,3142.1 1789.7,3143.8 1845.9,3194 1789.7,3194.8 1846.3,3237.7 1789.3,3238.9 1830.5,3277 1874.9,3276.7 1854,3302 2475,3390 2475,3435 1095,3515 1150,3515 1195,3515 2475,3520 2680,3640 2570,3695 2680,3695 2805,3695
  other v2: 1093.2,2286.7 1093.5,2324.5
HEXASPI_CLK: R62.1 U26.B2 | length 719.9
  Top Layer w5: R62.1@2607.72,1880 2621.86,1880 2626.86,1885 2626.86,1910 2631.86,1915 2642.93,1915 2647.91,1910.02 2647.91,1897.98 2652.89,1893 2664.93,1893 2669.91,1897.98 2669.91,1910 2674.91,1915 2787.56,1915 2895.56,1807 2961.78,1807 2990.35,1778.43 2990.35,1769 2985.35,1764 2979,1764 2974,1759 2974,1749 2978,1745 3001,1745 3006.13,1739.87 3006.13,1728.14 3001.12,1723.13 2979.12,1723.13 2972.39,1716.4 2972.39,1675.64 2978,1670.03 ; 2978,1670 2982.11,1665.89 v1(2996.76,1665.89)
  Bottom Layer w5: U26.B2@2979.88,1649.01 v1(2996.76,1665.89)
HEXASPI_DQS0: R58.1 U26.C3 | length 790.5
  Top Layer w5: R58.1@2607.72,1700 2620,1700 2737,1583 2775,1583 2780,1588 2780,1604 2797.59,1621.59 2804.59,1621.59 2820,1637 2862,1637 2873,1626 2933,1626 2950,1609 3061,1609 3065,1605 3065,1589 3070,1584 3085,1584 3090,1589 3090,1624 3085,1629 2959.87,1629 v1(2957.39,1626.52)
  Bottom Layer w5: U26.C3@2940.51,1609.64 v1(2957.39,1626.52)
HEXASPI_DQS1: R51.1 U26.B3 | length 827.3
  Top Layer w5: R51.1@2517.72,1880 2532,1880 2553.28,1858.72 2625.72,1858.72 2634.44,1850 2643.55,1850 2648.55,1855 2648.55,1873 2653.55,1878 2663.55,1878 2668.55,1873 2668.55,1855 2673.55,1850 2683.55,1850 2688.55,1855 2688.55,1895 2693.55,1900 2702.55,1900 2708.55,1894 2708.55,1855 2713.55,1850 2723.55,1850 2728.55,1855 2728.55,1895 2733.55,1900 2781.34,1900 2889.34,1792 2955.56,1792 2964,1783.56 2964,1774.61 2957.39,1768 v1(2957.39,1665.89)
  Bottom Layer w5: U26.B3@2940.51,1649.01 v1(2957.39,1665.89)
HEXASPI_IO0: R56.1 U26.D3 | length 770.7
  Top Layer w5: R56.1@2607.72,1610 2616.44,1601.28 2627.94,1601.28 2686,1543.22 2686,1461.66 2704.66,1443 2945,1443 2950,1448 2950,1457.92 2944.92,1463 2919,1463 2909,1473 2909,1534.04 2893.04,1550 2871,1550 2866,1555 2866,1566.75 2871,1571.75 2888,1571.75 2920.78,1571.77 2942.55,1550 2954,1550 v1(2957.39,1553.39)
  Bottom Layer w5: U26.D3@2940.51,1570.27 v1(2957.39,1553.39)
HEXASPI_IO1: R55.1 U26.D2 | length 723
  Top Layer w5: R55.1@2607.72,1565 2618.72,1554 2626,1554 2627,1553 2627.22,1553 2656,1524.22 2656,1449.22 2692.22,1413 2967.77,1413 2982.73,1427.96 2982.73,1481.81 2971.54,1493 2945,1493 2939,1499 2939,1530 2944,1535 2991.76,1535 2996.76,1540 v1(2996.76,1553.39)
  Bottom Layer w5: U26.D2@2979.88,1570.27 v1(2996.76,1553.39)
HEXASPI_IO2: R47.1 U26.C4 | length 878.1
  Top Layer w5: R47.1@2517.72,1700 2526.44,1691.28 2541.22,1691.28 2556.22,1676.28 2622.5,1676.28 2730.78,1568 2768.22,1568 2774.22,1562 2774.22,1519 2779.22,1514 2790,1514 2795,1519 2795,1597.78 2803.81,1606.59 2810.81,1606.59 2826.22,1622 2855,1622 2866,1611 2926.78,1611 2943.78,1594 3021,1594 3026,1589 3026,1571 3021,1566 3011,1566 3005,1572 2942.01,1572 2921.25,1592.76 v1(2918.02,1592.76)
  Bottom Layer w5: U26.C4@2901.14,1609.64 v1(2918.02,1592.76)
HEXASPI_IO3: R45.1 U26.D4 | length 758.1
  Top Layer w5: R45.1@2517.72,1610 2526.44,1601.28 2539.72,1601.28 2554.72,1586.28 2621.72,1586.28 2671,1537 2671,1455.44 2698.44,1428 2959.79,1428 2967.73,1435.94 2967.73,1473 2962.73,1478 2929,1478 2924,1483 2924,1543.79 v1(2918.4,1549.39)
  Bottom Layer w5: U26.D4@2901.14,1570.27 2918.4,1553.01 v1(2918.4,1549.39)
HEXASPI_IO4: R57.1 U26.D5 | length 706.7
  Top Layer w5: R57.1@2607.72,1655 2622.56,1655 2716,1561.56 2716,1478 2721,1473 2731,1473 2736,1478 2736,1548 2741,1553 2752,1553 2758,1547 2758,1502 2764,1496 2822,1496 2827.39,1501.39 2827.39,1511.99 2822.38,1517 2815,1517 2810,1522 2810,1536 2815,1541 2824,1541 2829,1546 2829,1558 2824,1563 2813,1563 2810,1566 2810,1584.56 2832.44,1607 2848,1607 2865.75,1589.25 v1(2880.75,1589.25)
  Bottom Layer w5: U26.D5@2861.77,1570.27 v1(2880.75,1589.25)
HEXASPI_IO5: R44.1 U26.E3 | length 745.3
  Top Layer w5: R44.1@2517.72,1565 2544.72,1538 2621,1538 2641,1518 2641,1443 2686,1398 2973.99,1398 2999,1423.01 2999,1486.76 2971.74,1514.02 v1(2957.39,1514.02)
  Bottom Layer w5: U26.E3@2940.51,1530.9 v1(2957.39,1514.02)
HEXASPI_IO6: R54.1 U26.E2 | length 670
  Top Layer w5: R54.1@2607.72,1515 2626,1496.72 2626,1434 2677,1383 3012,1383 3017,1388 3017,1509.02 3012,1514.02 v1(2996.76,1514.02)
  Bottom Layer w5: U26.E2@2979.88,1530.9 v1(2996.76,1514.02)
HEXASPI_IO7: R53.1 U26.E1 | length 672.3
  Top Layer w5: R53.1@2607.72,1470 2607.72,1430.28 2670,1368 3031,1368 3050,1387 3050,1500.15 v1(3036.58,1513.57)
  Bottom Layer w5: U26.E1@3019.25,1530.9 v1(3036.58,1513.57)
HEXASPI_IO8: R59.1 U26.C2 | length 753.6
  Top Layer w5: R59.1@2607.72,1745 2616.44,1736.28 2630.94,1736.28 2648.22,1719 2740,1719 2747,1712 2747,1711.78 2763.78,1695 2830.4,1695 2837.64,1687.76 2852.24,1687.76 2866,1674 2866,1659 2884,1641 2946,1641 2950,1645 3049.83,1645 3058,1653.17 3058,1680 3063,1685 3100,1685 3105.44,1679.56 3105.44,1657 3100.44,1652 v1(3081,1652)
  Bottom Layer w5: U26.C2@2979.88,1609.64 3001.24,1631 3060,1631 v1(3081,1652)
HEXASPI_IO9: R64.1 U26.B1 | length 641.2
  Top Layer w5: R64.1@2607.72,1965 2627.72,1945 2800,1945 2908,1837 2976,1837 3036.13,1776.87 v1(3036.13,1665.89)
  Bottom Layer w5: U26.B1@3019.25,1649.01 v1(3036.13,1665.89)
HEXASPI_IO10: R63.1 U26.A2 | length 643.5
  Top Layer w5: R63.1@2607.72,1920 2617.72,1930 2793.78,1930 2901.78,1822 2968,1822 3021.13,1768.87 3021.13,1688.4 3016.12,1683.39 2996.29,1683.39 2989.13,1690.55 2989.13,1697.63 v1(2996.76,1705.26)
  Bottom Layer w5: U26.A2@2979.88,1688.38 v1(2996.76,1705.26)
HEXASPI_IO11: R50.1 U26.A4 | length 770.8
  Top Layer w5: R50.1@2517.72,1835 2531.77,1835 2552.87,1813.9 2558.95,1813.9 2559.13,1813.72 2620.87,1813.72 2627.15,1820 2744.97,1820 2749.97,1815 2749.97,1784 2754.97,1779 2787,1779 2792,1774 2792,1745 2797,1740 2807,1740 2812,1745 2812,1774 2817,1779 2827,1779 2832,1774 2832,1745 2837,1740 2847,1740 2852,1745 2852,1766 2857,1771 2865,1771 2874.01,1761.99 2920.8,1761.99 2925.8,1756.99 2925.8,1731.8 2922,1728 2910,1728 2905,1733 2905,1742 2900,1747 2878,1747 2873,1742 2873,1731.13 2878,1726.13 2893.59,1726.13 2898.59,1721.13 2898.59,1711.59 2892.26,1705.26 v1(2884.26,1705.26)
  Bottom Layer w5: v1(2884.26,1705.26) U26.A4@2901.14,1688.38
HEXASPI_IO12: R49.1 U26.A5 | length 630.5
  Top Layer w5: R49.1@2517.72,1790 2531.77,1790 2539,1782.77 2539,1782.69 2552.79,1768.9 2558.95,1768.9 2559.13,1768.72 2630,1768.72 2635,1763.72 2635,1753.44 2645.9,1742.54 2653.54,1742.54 2661,1750 2661,1760 2643.54,1777.46 2643.54,1784.54 2649,1790 2673.77,1790 2678.59,1785.18 2678.59,1738.18 2682.77,1734 2694.41,1734 2698.59,1738.18 2698.59,1783 2703.59,1788 2714.97,1788 2719.97,1783 2719.97,1740.03 2725,1735 2737,1735 2740,1738 2740,1744 2745,1749 2757,1749 2762,1744 2762,1718 2770,1710 2840.15,1710 v1(2844.89,1705.26)
  Bottom Layer w5: v1(2844.89,1705.26) U26.A5@2861.77,1688.38
HEXASPI_IO13: R60.1 U26.B4 | length 579.4
  Top Layer w5: R60.1@2607.72,1790 2616.44,1798.72 2627.09,1798.72 2633.37,1805 2729.97,1805 2734.97,1800 2734.97,1771.02 2741.99,1764 2772,1764 2777,1759 2777,1730 2782,1725 2857.91,1725 2866.76,1716.15 2866.76,1694.46 2874.22,1687 2895,1687 2900,1682 2900,1675.81 2905,1670.81 2915.99,1670.81 2921,1675.82 2921,1688 2926,1693 2936,1693 2942.39,1686.61 2942.39,1675.64 2939.89,1673.14 2939.89,1661.89 2934,1656 2890.99,1656 2884.26,1662.73 v1(2884.26,1665.89)
  Bottom Layer w5: v1(2884.26,1665.89) U26.B4@2901.14,1649.01
HEXASPI_IO14: R48.1 U26.B5 | length 804.3
  Top Layer w5: R48.1@2517.72,1745 2531.22,1745 2539.22,1737 2548,1737 2553,1732 2553,1726.28 2558,1721.28 2624.72,1721.28 2642,1704 2656.38,1704 2661.38,1699 2661.38,1680 2666.38,1675 2676.38,1675 2681.38,1680 2681.38,1699 2686.38,1704 2696.38,1704 2701.38,1699 2701.38,1643 2706.38,1638 2715.38,1638 2721.38,1644 2721.38,1699 2726.38,1704 2733.56,1704 2742,1695.56 2742,1614 2746,1610 2763.96,1610 2770,1616.04 2770,1628 2762,1636 2762,1674 2767.99,1679.99 2769.99,1679.99 2780.56,1680 2785.56,1675 2785.56,1642.32 2791.29,1636.59 2798.37,1636.59 2805.56,1643.78 2805.56,1675 2810.56,1680 2819,1680 2824,1675 2824,1660 2832,1652 2842,1652 2844.89,1654.89 v1(2844.89,1665.89)
  Bottom Layer w5: v1(2844.89,1665.89) U26.B5@2861.77,1649.01
HEXASPI_IO15: R46.1 U26.C5 | length 861.9
  Top Layer w5: R46.1@2517.72,1655 2528.37,1655 2552.09,1631.28 2622.72,1631.28 2701,1553 2701,1467.88 2710.88,1458 2770.82,1458 2776,1463.18 2776,1476 2781,1481 2790.82,1481 2795.82,1476 2795.82,1463 2800.82,1458 2810.82,1458 2815.82,1463 2815.82,1476 2820.82,1481 2830.82,1481 2835.82,1476 2835.82,1463 2840.82,1458 2850.82,1458 2855.82,1463 2855.82,1475 2860.82,1480 2870.82,1480 2875.82,1475 2875.82,1463 2880.82,1458 2889,1458 2894,1463 2894,1488.97 2889,1493.97 2868,1493.97 2863,1498.97 2863,1508.97 2868,1513.97 2889,1513.97 2894,1518.97 2894,1527.82 2886.82,1535 2853,1535 2846,1542 2846,1553 2851,1558 2851,1579.01 v1(2841.07,1588.94)
  Bottom Layer w5: v1(2841.07,1588.94) U26.C5@2861.77,1609.64
HEXASPI_NCS: R61.1 R138.1 U26.A3 | length 974.6
  Top Layer w5: R61.1@2607.72,1835 2739.97,1835 2744.97,1840 2744.97,1880 2749.97,1885 2768,1885 2773.96,1879.04 2773.96,1871.95 2764.97,1862.96 2764.97,1799 2769.97,1794 2778.6,1794 2784.6,1800 2784.6,1859.6 2789.8,1864.8 2795.32,1864.8 2806.6,1853.52 2806.6,1799 2811.6,1794 2821.48,1794 2826.48,1799 2826.48,1816 2831.48,1821 2839.12,1821 2846.48,1813.64 2846.48,1799 2851.48,1794 2866.12,1794 2883.13,1776.99 2895.55,1776.99 2937.39,1777 2942.39,1772 2942.39,1714.44 2937.39,1709.44 v1(2919.45,1709.44)
  Bottom Layer w5: v1(2919.45,1709.44) U26.A3@2940.51,1688.38 2977.13,1725 3015,1725 3060,1680 R138.1@3117.29,1680
I2C2_SCL: R36.2 R68.2 R206.1 R226.2 U27.C14 | length 8588.1
  Top Layer w5: v1(2150,180) 2160,170 3030,170 3250,390 3543.79,390 3575,421.21 3575,695 3094,1176 2389.98,1176 2281.06,1284.92 2281.06,1326.22 2271.5,1335.78 2271.5,1375.34 2265.28,1381.56 2265.28,1405.02 2245,1425.3 R36.2@2245,1427.72 2268.64,1451.36 2292.51,1451.36 2301,1459.85 2301,1485 v2(2289,1497) ; R68.2@2600,2802.72 v1(2600,2850)
  L3_SIG w4: v1(1035,870) 1057.65,892.65 1319.32,892.65 1840,371.97 1916.08,371.97 1960.81,327.24 2084.73,327.24 2105.77,306.2 2113.8,306.2 2150,270 v1(2150,180) ; v2(2289,1497) 2291.01,1497 2306.01,1482 2331.68,1482 2343.68,1470 2405,1470 2438,1437 2637,1437 2665,1465 3165,1465 3251,1551 3251,1732.04 3392,1873.04 3392,1880.07 3392.97,1881.04 3392.97,1888.03 ; v1(2600,2850) 2675,2775 3110,2775 3150,2735 3465,2735 3572,2628 3572,2472.94 3393,2293.94 3393,1888.06
  Bottom Layer w5: R206.1@954.01,908.77 961.23,908.77 1000,870 v1(1035,870) ; v1(2150,180) R226.2@2150,207.28 ; v2(2289,1497) 2289,1499.21 U27.C14@2302.83,1513.03
I2C2_SDA: R38.2 R69.2 R202.1 R227.2 U27.B15 | length 8491.3
  Top Layer w5: v1(2110,180) 2105,180 2130,155 3036.22,155 3220.61,339.39 3338.17,339.39 3373.78,375 3550.01,375 3590,414.99 3590,705 3103.39,1191.61 2395.59,1191.61 2296.06,1291.14 2296.06,1328.94 2284,1341 2284,1354.43 2284.01,1375.56 2280,1379.57 2280,1415 2292.72,1427.72 R38.2@2305,1427.72 2313,1435.72 2313,1460.24 v2(2318.53,1465.77) ; R69.2@2655,2802.72 v1(2655,2850)
  L3_SIG w4: v1(1065,870) 1075,880 1315,880 1875,320 1946.12,320 1950.88,315.24 2079.76,315.24 2110,285 v1(2110,180) ; v2(2318.53,1465.77) 2324.23,1465.77 2369.69,1420.31 2418.81,1420.31 2424.5,1426 2482,1426 2496,1412 2628.98,1412 2669.98,1453 3173,1453 3263,1543 3263,1727.06 3404,1868.06 3404,1875.09 3404.97,1876.06 3404.97,1883.05 ; v1(2655,2850) 2716.76,2788.24 2758.25,2788.24 2759.15,2789.14 3115.86,2789.14 3155,2750 3470,2750 3584,2636 3584,2467.96 3405,2288.96 3405,1883.08
  Bottom Layer w5: R202.1@999.01,909.77 1018.78,890 1045,890 v1(1065,870) ; R227.2@2105,207.28 2105,185 v1(2110,180) ; v2(2318.53,1465.77) U27.B15@2334.33,1481.54
I_SENS_EXT_N: C27.1 C31.2 C32.2 CN2.2 R23.2 R24.2 U2.A2 | length 1638.7
  Top Layer w5: CN2.2@735,4180 785,4130 785,3960.36 955.36,3790 1615,3790 1771,3634 1771,3551.56 R24.2@1792.56,3530
  Top Layer w10: 1830.6,3363.6 U2.A2@1840,3354.2 ; 1840,3362.8 U2.A2@1840,3354.2 ; 1851.3,3361.3 U2.A2@1840,3350 U2.A2@1840,3354.2
  Top Layer w20: 1853.85,3361.81 C31.2@1895,3361.81 ; C31.2@1895,3362.56 C32.2@1945,3362.56 ; C32.2@1945,3362.52 1972.52,3362.52 1975,3365
I_SENS_EXT_P: CN2.1 LNK2.1 | length 1301.3
  Top Layer w5: CN2.1@735,4080 770,4045 770,3952.73 948.73,3774 1608.37,3774 1755,3627.37 1755,3618 1740,3603 LNK2.1@1740,3593.86
I_SENS_EXT_VDDCORE_N: C30.2 C53.1 CN2.4 R28.2 R30.1 R31.2 R35.2 | length 2611.8
  Top Layer w5: CN2.4@835,4180 885,4130 885,3977.63 1002.63,3860 1650,3860 1880,3630 1999.04,3630 2129.31,3499.73 2129.31,3259.31 2095,3225 2081,3225 2065,3209 2065,3197.56 R35.2@2082.56,3180 ; R28.2@1665,3247.28 C30.2@1710,3247.28 1710,3230 v1(1720,3220)
  L3_SIG w4: v1(1720,3220) 1767.7,3172.3 1957.7,3172.3 v1(2135,2995)
I_SENS_EXT_VDDCORE_P: C42.2 C49.2 C53.2 C56.2 C62.2 CN2.3 L5.2 R31.1 R35.1 | length 1924.5
  Top Layer w5: CN2.3@835,4080 869,4046 869,3971 996,3844 1643.37,3844 1873.37,3614 1992.41,3614 2115.4,3491.01 2115.4,3265.4 2090,3240 2075,3240 2050,3215 2050,3202.56 R35.1@2027.44,3180
I_SENS_INT_N: C15.2 C16.2 C23.1 C24.2 CN2.6 R19.2 R20.2 U1.1 U1.6 | length 2695.9
  Top Layer w5: R20.2@1372.45,2235 1390,2252.56 1390,2325 1414,2349 1414,2581 v1(1410,2585)
  Top Layer w10: 1290,1850 1297.21,1857.21 U1.6@1297.21,1881.93 1297.21,1892.69 1297.28,1892.76
  Top Layer w20: v1(1230,1795) 1252.56,1817.56 C16.2@1252.56,1830 ; v1(1235,1865) 1252.56,1847.44 C16.2@1252.56,1830 ; 1290,1850 1270,1830 C16.2@1252.56,1830 ; U1.1@1349,1989 1348.39,1989.61 U1.1@1348.39,1998.07 ; 1351.82,2125 R19.2@1372.45,2125 ; 1351.82,2180 C23.1@1372.45,2180 ; 1351.82,2235 R20.2@1372.45,2235 1372.44,2207.29 ; 1363.3,1998.07 U1.1@1348.39,1998.07 ; 1364.22,2050 C24.2@1382.29,2050 ; 1372.44,2097.29 R19.2@1372.45,2125 ; 1372.44,2152.71 R19.2@1372.45,2125 ; 1372.44,2154.46 C23.1@1372.45,2180 ; 1372.44,2205.54 C23.1@1372.45,2180 ; v1(1380,2020) 1376.92,2016.92 1348.39,2016.92 U1.1@1348.39,1998.07 ; 1382.28,2030.95 C24.2@1382.29,2050 ; 1382.28,2069.05 C24.2@1382.29,2050
  Bottom Layer w5: CN2.6@935,4180 985,4130 985,3985 1445,3525 1445,2620 v1(1410,2585)
  other v1: 1380,2085
I_SENS_INT_P: CN2.5 LNK1.1 | length 1999.8
  Top Layer w5: v1(1409.77,2610.23) 1417,2603 1417.46,2603 1428,2592.46 1428,2592 1430,2590 1430,2341.75 1412,2323.75 LNK1.1@1412,2308.86
  Bottom Layer w5: CN2.5@935,4080 969,4046 969,3971 1429,3511 1429,2629.46 v1(1409.77,2610.23)
I_SENS_INT_VDDCORE_N: C170.2 CN2.10 R22.2 R167.1 R168.1 U27.G2 | length 3401.4
  Top Layer w5: CN2.10@1135,4180 1085,4130 1085,4040 1230,3895 1490,3895 v1(1510,3915)
  Top Layer w10: 1681,1830 1681,1717 1746,1652 1891,1652 1910.43,1632.57 v2(1910.43,1624.58)
  Top Layer w20: 1657.29,1872.44 R22.2@1685,1872.44 ; 1685,1851.82 R22.2@1685,1872.44 ; 1712.71,1872.44 R22.2@1685,1872.44
  Bottom Layer w5: v1(1510,3915) 1510,3907.63 1536,3881.63 1536,2101.78 1656.78,1981 1665.75,1981 1679,1981.01 1699.16,1960.85 1699.16,1943.4 R168.1@1717.56,1925
  Bottom Layer w10: v2(1910.43,1624.58) U27.G2@1924.88,1639.02
  Bottom Layer w20: 1740,1825 R167.1@1717.56,1825 C170.2@1717.56,1875 ; 1740,1875 C170.2@1717.56,1875 ; 1745,1915 1735,1925 R168.1@1717.56,1925 C170.2@1717.56,1875
  other v2: 1754,1831 1745,1850 1764,1857 1765.3,1876.3 1747,1887
I_SENS_INT_VDDCORE_P: C170.1 C176.2 C177.2 C178.2 C179.2 CN2.9 L7.1 R167.2 R168.2 | length 3116.8
  Top Layer w5: CN2.9@1135,4080 1135,4015 1239,3911 1471,3911 v1(1477.5,3917.5)
  Bottom Layer w5: v1(1477.5,3917.5) 1520,3875 1520,2095.15 1650.15,1965 1672.38,1965 1680,1957.38 1680,1942.56 R168.2@1662.45,1925
  Bottom Layer w20: 1504.97,1804.57 C178.2@1530.51,1804.57 ; 1504.97,1884.45 C179.2@1530.51,1884.45 ; 1530.51,1825.19 C178.2@1530.51,1804.57 ; 1530.51,1863.83 C179.2@1530.51,1884.45 ; 1556.05,1804.57 C178.2@1530.51,1804.57 ; 1556.05,1884.45 C179.2@1530.51,1884.45 ; 1564.97,1804.57 C176.2@1590.51,1804.57 ; 1564.97,1884.45 C177.2@1590.51,1884.45 ; 1590.51,1825.19 C176.2@1590.51,1804.57 ; 1590.51,1863.83 C177.2@1590.51,1884.45 ; 1616.05,1804.57 C176.2@1590.51,1804.57 ; 1616.05,1884.45 C177.2@1590.51,1884.45 ; 1625,1796.28 L7.1@1652.77,1768.51 ; 1636.61,1825 R167.2@1662.45,1825 ; 1638.93,1875 C170.1@1662.45,1875 ; R168.2@1662.45,1925 C170.1@1662.45,1875 ; L7.1@1666,1735 1666,1804 1662.44,1807.56 R167.2@1662.45,1825 ; R167.2@1662.45,1825 C170.1@1662.45,1875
